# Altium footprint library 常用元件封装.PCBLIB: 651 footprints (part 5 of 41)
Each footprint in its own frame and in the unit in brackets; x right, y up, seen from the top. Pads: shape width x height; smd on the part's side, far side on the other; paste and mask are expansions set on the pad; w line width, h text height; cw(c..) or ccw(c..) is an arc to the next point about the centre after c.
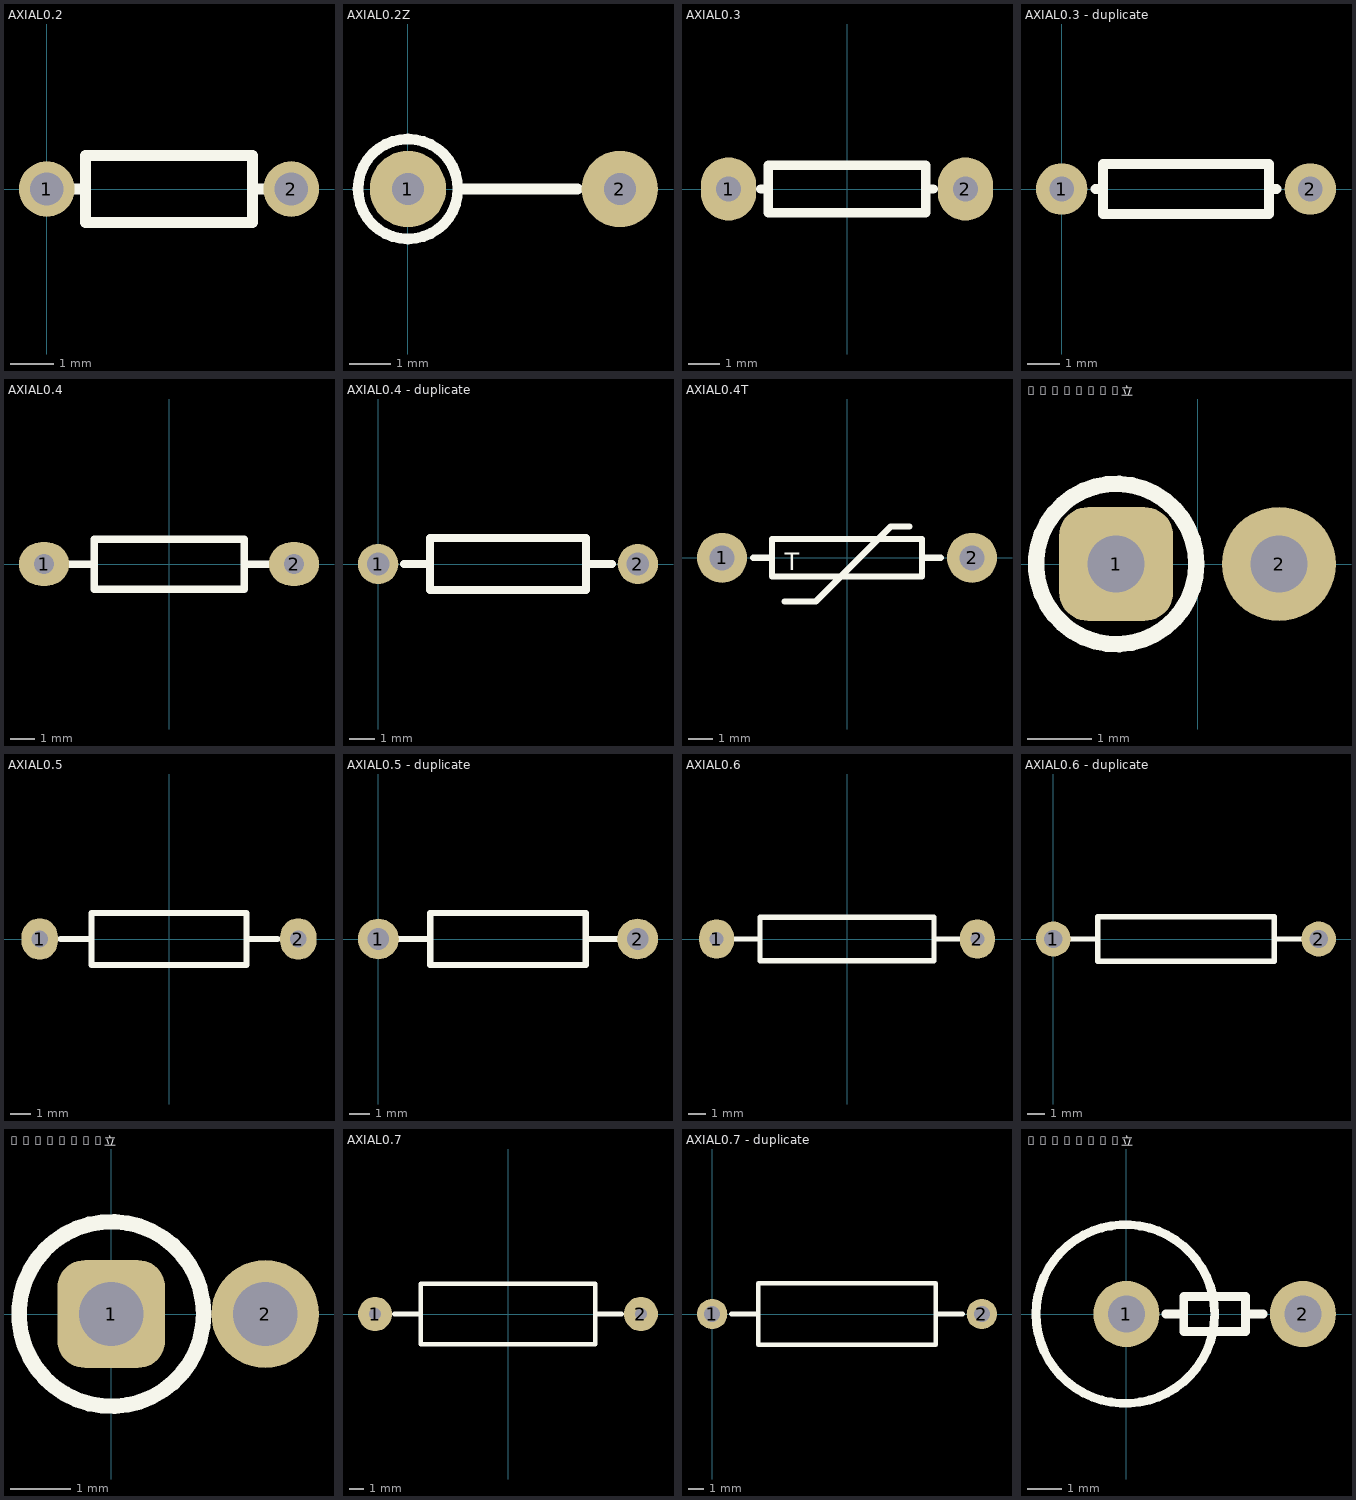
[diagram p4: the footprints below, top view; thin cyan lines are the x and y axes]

## AXIAL0.2 [mil]
pads (2):
  round 50 hole 30: 1(0,0) 2(220,0)
TopOverlay:
  lines w10: 25,0 35,0 ; 184,-30 35,-30 35,30 184,30 ; 185,-30 185,30 ; 185,0 195,0

## AXIAL0.2Z [mil]
pads (2):
  round 72 hole 30: 1(0,0) 2(200,0)
TopOverlay:
  circle w10: c0,0 r47.17
  lines w10: 50,0 160,0

## AXIAL0.3 [mil]
pads (2):
  oval 70x80 hole 32: 1(-150,0) 2(150,0)
TopOverlay:
  lines w12: -109,0 -100,0 ; 109,0 100,0 ; 100,0 100,-30 -100,-30 -100,30 100,30 100,0

## AXIAL0.3 - duplicate [mil] "7.62mm 1/8W 1/4W"
pads (2):
  round 62 hole 30: 1(0,0) 2(300,0)
TopOverlay:
  lines w12: 41,0 50,0 ; 259,0 250,0 ; 250,0 250,30 50,30 50,-30 250,-30 250,0

## AXIAL0.4 [mil]
pads (2):
  oval 80x70 hole 32: 1(-200,0) 2(200,0)
TopOverlay:
  lines w12: -160,0 -120,0 ; 120,0 160,0 ; -120,-40 -120,40 120,40 120,-40 -120,-40

## AXIAL0.4 - duplicate [mil] "10.16mm 1/4W 1/2W"
pads (2):
  round 62 hole 35: 1(0,0) 2(400,0)
TopOverlay:
  lines w12: 40,0 80,0 ; 320,0 360,0 ; 80,-40 80,40 320,40 320,-40 80,-40

## AXIAL0.4T [mil]
pads (2):
  round 80 hole 40: 1(-200,0) 2(200,0)
TopOverlay:
  lines w10: -150,0 -120,0 ; -100,-70 -50,-70 70,50 100,50 ; 120,0 150,0 ; -120,-30 120,-30 120,30 -120,30 -120,-30
  text "T" at -100,-20 h28

## AXIAL0.4立 [mil] "2.54mm"
pads (2):
  rrect50% 70x70 hole 35: 1(-50,0)
  round 70 hole 35: 2(50,0)
TopOverlay:
  circle w10: c-50,0 r49.24

## AXIAL0.5 [mil]
pads (2):
  oval 70x80 hole 32: 1(-250,0) 2(250,0)
TopOverlay:
  lines w12: -210,0 -150,0 ; 150,0 210,0 ; -150,-50 150,-50 150,50 -150,50 -150,-50

## AXIAL0.5 - duplicate [mm] "12.7mm 1/2W"
pads (2):
  round 2 hole 1.062: 1(0,0) 2(12.7,0)
TopOverlay:
  lines w0.305: 1.016,0 2.54,0 ; 10.16,0 11.684,0 ; 2.54,-1.27 2.54,1.27 10.16,1.27 10.16,-1.27 2.54,-1.27

## AXIAL0.6 [mil]
pads (2):
  oval 80x90 hole 32: 1(-300,0) 2(300,0)
TopOverlay:
  lines w12: -260,0 -200,0 ; 200,0 260,0 ; -200,-50 -200,50 200,50 200,-50 -200,-50

## AXIAL0.6 - duplicate [mm] "15.24mm 1W 2W"
pads (2):
  round 2 hole 1.062: 1(0,0) 2(15.24,0)
TopOverlay:
  lines w0.305: 1.016,0 2.54,0 ; 12.7,0 14.224,0 ; 2.54,-1.27 2.54,1.27 12.7,1.27 12.7,-1.27 2.54,-1.27

## AXIAL0.6立 [mil] "3.048mm"
pads (2):
  rrect50% 70x70 hole 41.81: 1(0,0)
  round 70 hole 41.81: 2(100,0)
TopOverlay:
  circle w10: c0,0 r60

## AXIAL0.7 [mil]
pads (2):
  round 90 hole 32: 1(-350,0) 2(350,0)
TopOverlay:
  lines w12: -300,0 -230,0 ; 230,0 300,0 ; -230,-80 -230,80 230,80 230,-80 -230,-80

## AXIAL0.7 - duplicate [mm] "17.78mm 2W 3W"
pads (2):
  round 2 hole 1.062: 1(0,0) 2(17.78,0)
TopOverlay:
  lines w0.305: 1.27,0 3.048,0 ; 14.732,0 16.51,0 ; 3.048,-2.032 14.732,-2.032 14.732,2.032 3.048,2.032 3.048,-2.032

## AXIAL0.7立 [mil] "5.08mm"
pads (2):
  round 75 hole 41.81: 1(0,0) 2(200,0)
TopOverlay:
  circle w10: c-1.24,0 r101.24
  lines w10: 45,0 65,0 ; 135,0 155,0 ; 65,-20 135,-20 135,20 65,20 65,-20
